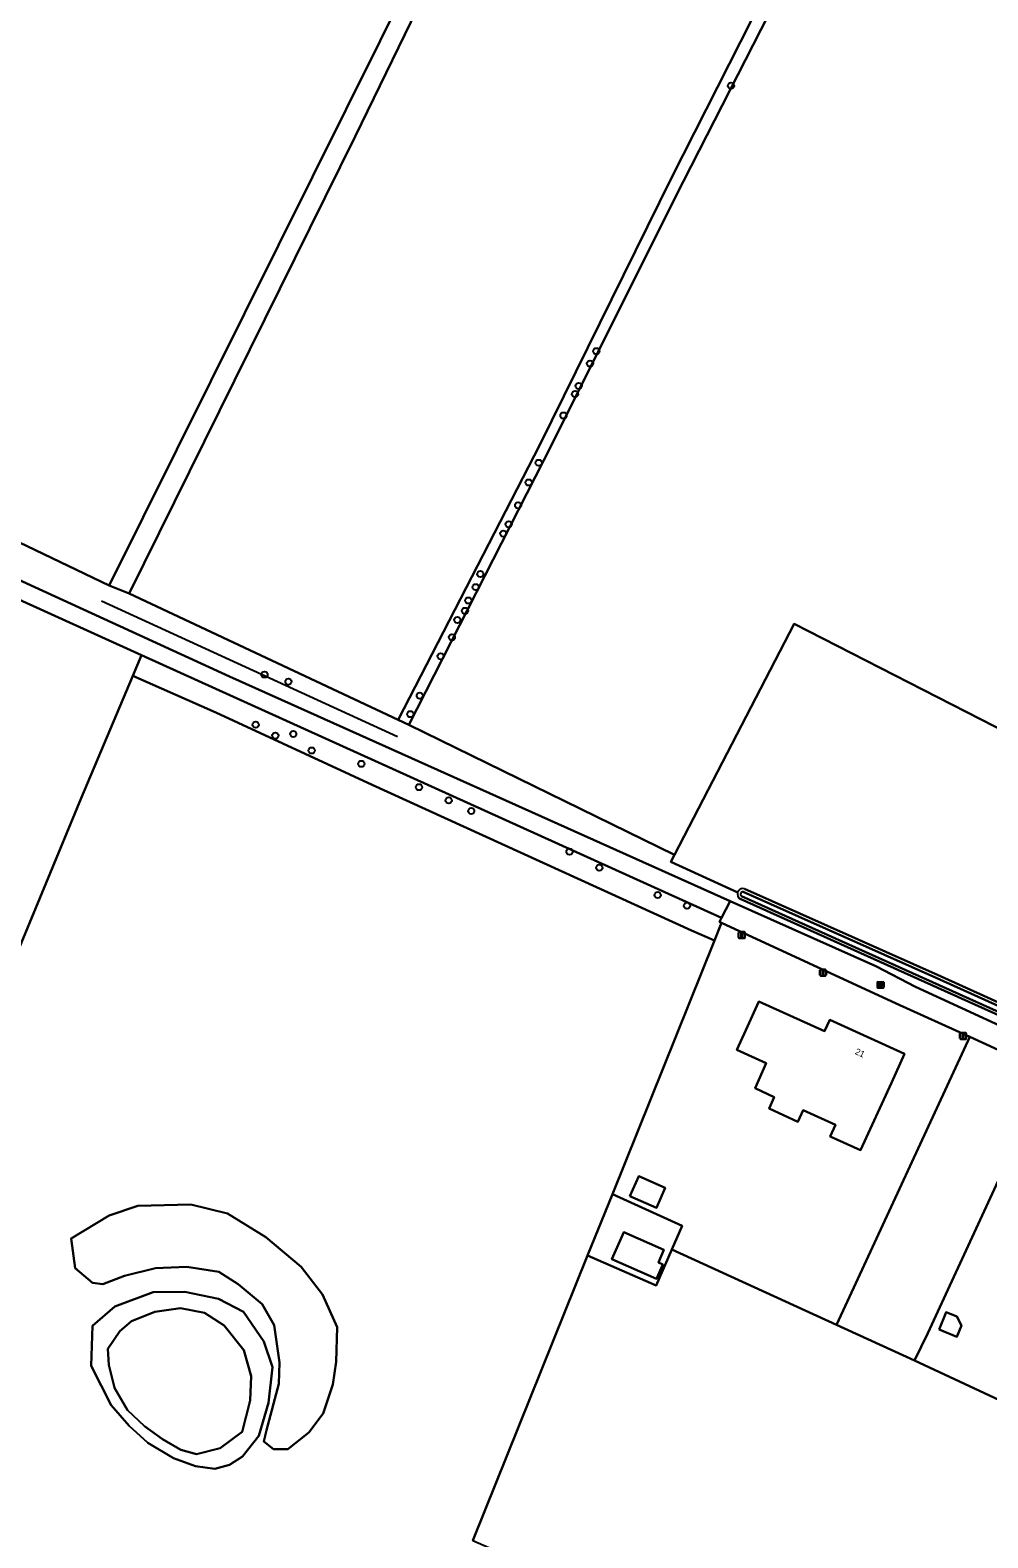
# Model space of a CAD drawing. Extents: x 155209 to 156748, y 385356 to 388487.
# Drawn here: x 155626.8 to 155777.4, y 385972.7 to 386210 of the extents above; entities that cross this region are included whole.
import ezdxf

# ---------------------------------------------------------------- set-up
doc = ezdxf.new("R2010")
doc.units = 0
for name, color, linetype in [('IMGEO_Boom', 7, 'Continuous'), ('IMGEO_Bouwland', 7, 'Continuous'), ('IMGEO_Erf', 7, 'Continuous'), ('IMGEO_Grasland_agrarisch', 7, 'Continuous'), ('IMGEO_Grasland_overig', 7, 'Continuous'), ('IMGEO_Groenvoorziening', 7, 'Continuous'), ('IMGEO_Hek', 7, 'Continuous'), ('IMGEO_Houtwal', 7, 'Continuous'), ('IMGEO_Lichtmast', 7, 'Continuous'), ('IMGEO_Loofbos', 7, 'Continuous'), ('IMGEO_Meer_plas_ven_vijver', 7, 'Continuous'), ('IMGEO_Oever', 7, 'Continuous'), ('IMGEO_Pand', 7, 'Continuous'), ('IMGEO_Pand_nummerreeks', 7, 'Continuous'), ('IMGEO_Rijbaan_lokaal_open', 7, 'Continuous'), ('IMGEO_Rioolput', 7, 'Continuous'), ('IMGEO_Waterloop', 7, 'Continuous')]:
    doc.layers.add(name, color=color, linetype=linetype)

msp = doc.modelspace()

# ---------------------------------------------------------------- linework, layer by layer
at = {"layer": 'IMGEO_Boom'}
for centre in [(155737.01, 386201.25), (155715.85, 386159.47), (155714.83, 386157.52), (155713.05, 386154), (155712.48, 386152.72), (155710.67, 386149.34), (155706.75, 386141.9), (155705.18, 386138.8), (155703.53, 386135.19), (155701.19, 386130.76), (155702.06, 386132.22), (155697.6, 386124.38), (155696.85, 386122.33), (155695.19, 386118.6), (155695.7, 386120.23), (155693.97, 386117.17), (155693.11, 386114.44), (155691.34, 386111.45), (155663.63, 386108.57), (155667.4, 386107.46), (155688.06, 386105.24), (155686.57, 386102.34), (155662.25, 386100.67), (155668.15, 386099.23), (155665.35, 386098.96), (155671.06, 386096.62), (155678.86, 386094.52), (155687.95, 386090.85), (155692.62, 386088.76), (155696.15, 386087.09), (155711.61, 386080.69), (155716.3, 386078.17), (155725.49, 386073.86), (155730.09, 386072.18)]:
    msp.add_circle(centre, 0.489, dxfattribs=at)
at = {"layer": 'IMGEO_Bouwland'}
msp.add_lwpolyline([(155732.88, 386307.56), (155732.51, 386306.84), (155728.48, 386298.72), (155729.99, 386297.98), (155708.82, 386256.23), (155704.36, 386246.76), (155689.59, 386217.32), (155677.91, 386193.26), (155642.36, 386121.35), (155684.67, 386101.45), (155706.93, 386144.74), (155727.66, 386186.74), (155753.06, 386236.87), (155775.47, 386280.18), (155776.23, 386279.85), (155779.73, 386287.01), (155779.22, 386287.22)], close=True, dxfattribs=at)
for points in [[(155823.3, 386267.6), (155780.71, 386286.96), (155779.89, 386287.34), (155779.73, 386287.01), (155776.23, 386279.85), (155777.11, 386279.38), (155729.56, 386186.22), (155707.56, 386142.3), (155686.33, 386100.64), (155728.14, 386080.19), (155746.94, 386116.53), (155834.92, 386071.53), (155850.53, 386101.48), (155869.89, 386139.18), (155897.23, 386193.45), (155910.33, 386221.05), (155911.39, 386223.4)], [(155606.88, 386138.08), (155639.2, 386122.59), (155681.83, 386208.31), (155708.36, 386261.64)]]:
    msp.add_lwpolyline(points, dxfattribs=at)
at = {"layer": 'IMGEO_Erf'}
for points in [[(155773.63, 386049.48), (155774.57, 386051.53), (155763.02, 386056.8), (155735.55, 386069.49), (155734.42, 386066.69), (155718.37, 386026.8), (155729.32, 386021.82), (155727.71, 386018.1), (155753.63, 386006.21), (155755.36, 386009.95)], [(155743, 386040.26), (155743.83, 386042.08), (155740.8, 386043.46), (155742.57, 386047.38), (155737.92, 386049.5), (155739.33, 386052.58), (155741.41, 386057.13), (155751.74, 386052.44), (155752.57, 386054.25), (155764.33, 386048.88), (155762.26, 386044.33), (155757.4, 386033.69), (155752.64, 386035.86), (155753.47, 386037.68), (155748.37, 386040.01), (155747.54, 386038.19)], [(155853.12, 385955.51), (155846.2, 385958.41), (155852.48, 385973.4), (155859.4, 385970.5), (155868.12, 385991.46), (155867.03, 385991.83), (155872.65, 386005.2), (155873.35, 386006.89), (155838.02, 386023), (155837.33, 386022.91), (155786.93, 386045.9), (155786.05, 386043.98), (155767.96, 386004.93), (155765.9, 386000.59), (155785.57, 385991.44), (155812.34, 385978.74), (155809.88, 385972.63), (155808.05, 385968.03), (155801.87, 385953.41), (155776.85, 385893.52), (155754.19, 385839.25), (155761.09, 385835.71), (155796.45, 385820.47), (155833.54, 385909.24)], [(155721.12, 386026.45), (155722.5, 386029.61), (155726.68, 386027.78), (155725.31, 386024.62)], [(155769.75, 386005.48), (155770.87, 386008.2), (155772.55, 386007.51), (155773.26, 386006.1), (155772.53, 386004.34)]]:
    msp.add_lwpolyline(points, close=True, dxfattribs=at)
at = {"layer": 'IMGEO_Grasland_agrarisch'}
msp.add_lwpolyline([(155785.57, 385991.44), (155765.9, 386000.59), (155753.63, 386006.21), (155727.71, 386018.1), (155725.24, 386012.39), (155714.46, 386017.11), (155696.41, 385972.27), (155741.48, 385952.55), (155743.7, 385951.54), (155749.58, 385965.64), (155754.11, 385964.04), (155732.64, 385910.57), (155730.66, 385911.1), (155728.52, 385911.95), (155741.86, 385947.1), (155694.61, 385967.79), (155668.77, 385903.59), (155694.55, 385871.44), (155696.18, 385869.04), (155744.28, 385815.73), (155754.19, 385839.25), (155776.85, 385893.52), (155771.51, 385895.43), (155790.82, 385938.59)], dxfattribs=at)
at = {"layer": 'IMGEO_Grasland_overig'}
for points in [[(155504.09, 386155.62), (155505.6, 386152.12), (155509.32, 386155.77), (155513.88, 386157.83), (155518.84, 386160.07), (155521.55, 386160.07), (155524.55, 386160.06), (155540.9, 386154.4), (155549.79, 386151.41), (155559.26, 386147.86), (155579.62, 386140.7), (155590.17, 386136.48), (155623.23, 386121.15), (155644.28, 386111.61), (155735.52, 386070.28), (155736.9, 386072.88), (155658.12, 386108.28)], [(155658.12, 386108.28), (155598.08, 386135.8), (155590.64, 386139.37), (155577.96, 386145.45), (155574.75, 386146.49), (155547.27, 386157.72)]]:
    msp.add_lwpolyline(points, dxfattribs=at)
for points in [[(155767.96, 386004.93), (155786.05, 386043.98), (155786.93, 386045.9), (155774.57, 386051.53), (155773.63, 386049.48), (155755.36, 386009.95), (155753.63, 386006.21), (155765.9, 386000.59)], [(155729.32, 386021.82), (155718.37, 386026.8), (155714.46, 386017.11), (155725.24, 386012.39), (155727.71, 386018.1)], [(155720.14, 386020.83), (155726.48, 386018.02), (155725.6, 386016.02), (155726.28, 386015.72), (155725.28, 386013.44), (155718.25, 386016.55)]]:
    msp.add_lwpolyline(points, close=True, dxfattribs=at)
at = {"layer": 'IMGEO_Groenvoorziening'}
for points in [[(155639.2, 386122.59), (155606.88, 386138.08), (155552.95, 386161.21), (155559.66, 386175.91), (155576.44, 386207.57), (155574.39, 386208.21), (155571.97, 386208.45), (155571.62, 386207.25), (155570.5, 386204.77), (155549.02, 386162.14)], [(155549.69, 386159.71), (155563.67, 386153.1), (155579.39, 386146.58), (155591.1, 386142.16), (155584.82, 386143.24), (155577.96, 386145.45), (155590.64, 386139.37), (155598.08, 386135.8), (155658.12, 386108.28), (155736.9, 386072.88), (155759.83, 386062.69), (155766.03, 386059.41), (155780.61, 386052.71), (155832.25, 386029.22), (155834.86, 386028.6), (155915.05, 385991.74), (155919.39, 385989.89), (155919.66, 385990.52), (155920.08, 385991.51), (155916.27, 385993.23), (155901.28, 386000), (155841.09, 386027.17), (155813.87, 386039.65)], [(155738.07, 386074.28), (155727.58, 386079.11), (155728.14, 386080.19), (155686.33, 386100.64), (155684.67, 386101.45), (155642.36, 386121.35), (155639.2, 386122.59)], [(155696.41, 385972.27), (155714.46, 386017.11), (155718.37, 386026.8), (155734.42, 386066.69), (155730.79, 386068.29), (155680.57, 386091.23), (155655.98, 386102.58), (155642.9, 386108.36), (155634.78, 386089.14), (155623.77, 386062.46), (155612.62, 386034.06), (155600.72, 386002.52), (155602.52, 386000), (155614.21, 385983.64), (155617.02, 385979.21), (155622.46, 385969.1)], [(155807.53, 386042.14), (155738.44, 386073.25)]]:
    msp.add_lwpolyline(points, dxfattribs=at)
for points in [[(155735.2, 386069.65), (155735.52, 386070.28), (155644.28, 386111.61), (155642.9, 386108.36), (155655.98, 386102.58), (155680.57, 386091.23), (155730.79, 386068.29), (155734.42, 386066.69), (155735.55, 386069.49)], [(155643.73, 386024.97), (155652.02, 386025.17), (155657.79, 386023.76), (155663.86, 386020.01), (155669.42, 386015.36), (155672.75, 386011.01), (155675.08, 386005.85), (155674.88, 386000.39), (155674.37, 385996.84), (155672.85, 385992.29), (155670.63, 385989.26), (155667.29, 385986.63), (155665.07, 385986.63), (155663.55, 385987.84), (155663.96, 385989.66), (155665.88, 385996.95), (155665.98, 386000.28), (155665.17, 386006.15), (155663.25, 386009.49), (155659.51, 386012.63), (155656.47, 386014.55), (155651.42, 386015.36), (155646.46, 386015.16), (155641.61, 386013.94), (155638.19, 386012.64), (155636.56, 386012.83), (155633.83, 386015.16), (155633.22, 386019.81), (155639.18, 386023.45)], [(155660.16, 385985.51), (155658.12, 385984.21), (155655.81, 385983.53), (155652.78, 385983.95), (155649.29, 385985.26), (155645.26, 385987.65), (155642.36, 385990.3), (155639.5, 385993.56), (155636.36, 385999.79), (155636.59, 386006.08), (155640.11, 386009.09), (155646.11, 386011.35), (155651.1, 386011.4), (155656.42, 386010.29), (155660.34, 386008.25), (155663.53, 386003.59), (155664.87, 385999.56), (155664.27, 385993.97), (155662.74, 385988.75)]]:
    msp.add_lwpolyline(points, close=True, dxfattribs=at)
msp.add_arc((155738.9, 386074), 0.881, 161.5794, 238.3689, dxfattribs=at)
at = {"layer": 'IMGEO_Hek'}
for points in [[(155637.98, 386120.16), (155684.58, 386098.82)], [(155728.14, 386080.19), (155746.94, 386116.53)], [(155680.57, 386091.23), (155655.98, 386102.58), (155642.9, 386108.36)], [(155680.57, 386091.23), (155730.79, 386068.29)], [(155734.42, 386066.69), (155730.79, 386068.29)]]:
    msp.add_lwpolyline(points, dxfattribs=at)
at = {"layer": 'IMGEO_Houtwal'}
for points in [[(155639.2, 386122.59), (155642.36, 386121.35), (155677.91, 386193.26), (155689.59, 386217.32), (155704.36, 386246.76), (155708.82, 386256.23), (155729.99, 386297.98), (155728.48, 386298.72), (155726.94, 386299.43), (155724.52, 386294.86), (155708.36, 386261.64), (155681.83, 386208.31)], [(155776.23, 386279.85), (155775.47, 386280.18), (155753.06, 386236.87), (155727.66, 386186.74), (155706.93, 386144.74), (155684.67, 386101.45), (155686.33, 386100.64), (155707.56, 386142.3), (155729.56, 386186.22), (155777.11, 386279.38)]]:
    msp.add_lwpolyline(points, close=True, dxfattribs=at)
at = {"layer": 'IMGEO_Lichtmast'}
for p, q in [((155738.21, 386067.16), (155738.21, 386067.96)), ((155738.21, 386067.96), (155738.21, 386067.16)), ((155738.31, 386068.06), (155739.1, 386068.06)), ((155739.1, 386068.06), (155738.31, 386068.06)), ((155739.1, 386067.06), (155738.31, 386067.06)), ((155738.31, 386067.06), (155739.1, 386067.06)), ((155739.2, 386067.96), (155739.2, 386067.16)), ((155739.2, 386067.16), (155739.2, 386067.96)), ((155751.01, 386061.25), (155751.01, 386062.05)), ((155751.01, 386062.05), (155751.01, 386061.25)), ((155751.11, 386062.15), (155751.89, 386062.15)), ((155751.89, 386062.15), (155751.11, 386062.15)), ((155751.99, 386062.05), (155751.99, 386061.25)), ((155751.99, 386061.25), (155751.99, 386062.05)), ((155751.89, 386061.15), (155751.11, 386061.15)), ((155751.11, 386061.15), (155751.89, 386061.15)), ((155773.14, 386052.18), (155773.93, 386052.18)), ((155773.93, 386052.18), (155773.14, 386052.18)), ((155773.04, 386051.28), (155773.04, 386052.08)), ((155773.04, 386052.08), (155773.04, 386051.28)), ((155773.93, 386051.18), (155773.14, 386051.18)), ((155773.14, 386051.18), (155773.93, 386051.18)), ((155774.03, 386052.08), (155774.03, 386051.28)), ((155774.03, 386051.28), (155774.03, 386052.08))]:
    msp.add_line(p, q, dxfattribs=at)
for points in [[(155738.63, 386067.93), (155738.78, 386067.93), (155738.78, 386067.18), (155738.63, 386067.18), (155738.63, 386067.93)], [(155751.43, 386062.03), (155751.58, 386062.03), (155751.58, 386061.28), (155751.43, 386061.28), (155751.43, 386062.03)], [(155773.46, 386052.06), (155773.61, 386052.06), (155773.61, 386051.31), (155773.46, 386051.31), (155773.46, 386052.06)]]:
    msp.add_lwpolyline(points, dxfattribs=at)
for centre, start, end in [((155738.31, 386067.96), 90, 180), ((155738.31, 386067.96), 90, 180), ((155738.31, 386067.16), 180, 270), ((155738.31, 386067.16), 180, 270), ((155739.1, 386067.96), 0, 90), ((155739.1, 386067.96), 360, 90), ((155739.1, 386067.16), 270, 0), ((155739.1, 386067.16), 270, 0), ((155751.11, 386062.05), 90, 180), ((155751.11, 386062.05), 90, 180), ((155751.89, 386062.05), 0, 90), ((155751.89, 386062.05), 360, 90), ((155751.11, 386061.25), 180, 270), ((155751.11, 386061.25), 180, 270), ((155751.89, 386061.25), 270, 0), ((155751.89, 386061.25), 270, 0), ((155773.14, 386052.08), 90, 180), ((155773.14, 386052.08), 90, 180), ((155773.93, 386052.08), 0, 90), ((155773.93, 386052.08), 360, 90), ((155773.14, 386051.28), 180, 270), ((155773.14, 386051.28), 180, 270), ((155773.93, 386051.28), 270, 0), ((155773.93, 386051.28), 270, 0)]:
    msp.add_arc(centre, 0.1, start, end, dxfattribs=at)
at = {"layer": 'IMGEO_Loofbos'}
for points in [[(155642.9, 386108.36), (155644.28, 386111.61), (155623.23, 386121.15), (155590.17, 386136.48), (155577.59, 386140.01), (155524.61, 386153.45), (155547.77, 386103.46), (155550.82, 386095.86), (155552.73, 386090.35), (155554.74, 386085.49), (155557.92, 386078.77), (155562.83, 386070.3), (155563.7, 386067.74), (155564.93, 386064.75), (155568.14, 386057.92), (155570.58, 386052.33), (155572.95, 386047.52), (155579.19, 386036.04), (155588.18, 386021.54), (155595.93, 386009.42), (155600.72, 386002.52), (155612.62, 386034.06), (155623.77, 386062.46), (155634.78, 386089.14)], [(155670.63, 385989.26), (155672.85, 385992.29), (155674.37, 385996.84), (155674.88, 386000.39), (155675.08, 386005.85), (155672.75, 386011.01), (155669.42, 386015.36), (155663.86, 386020.01), (155657.79, 386023.76), (155652.02, 386025.17), (155643.73, 386024.97), (155639.18, 386023.45), (155633.22, 386019.81), (155633.83, 386015.16), (155636.56, 386012.83), (155638.19, 386012.64), (155641.61, 386013.94), (155646.46, 386015.16), (155651.42, 386015.36), (155656.47, 386014.55), (155659.51, 386012.63), (155663.25, 386009.49), (155665.17, 386006.15), (155665.98, 386000.28), (155665.88, 385996.95), (155663.96, 385989.66), (155663.55, 385987.84), (155665.07, 385986.63), (155667.29, 385986.63)]]:
    msp.add_lwpolyline(points, close=True, dxfattribs=at)
for points in [[(155821.1, 386039.46), (155837.21, 386070.36), (155834.92, 386071.53), (155746.94, 386116.53), (155728.14, 386080.19), (155727.58, 386079.11), (155738.07, 386074.28)], [(155739.12, 386074.85), (155770.1, 386061.03), (155808.28, 386043.75)]]:
    msp.add_lwpolyline(points, dxfattribs=at)
msp.add_arc((155738.9, 386074), 0.879, 75.7492, 161.4105, dxfattribs=at)
at = {"layer": 'IMGEO_Meer_plas_ven_vijver'}
msp.add_lwpolyline([(155652.95, 385985.88), (155656.66, 385986.82), (155660.13, 385989.36), (155661.38, 385994.3), (155661.51, 385998.14), (155660.36, 386002.25), (155657.26, 386006.09), (155654.21, 386008.12), (155650.43, 386008.82), (155646.36, 386008.26), (155642.71, 386006.78), (155640.89, 386005.23), (155639.01, 386002.45), (155639.15, 385999.9), (155640.03, 385996.29), (155642.1, 385992.78), (155644.74, 385990.27), (155647.61, 385988.2), (155650.47, 385986.56)], close=True, dxfattribs=at)
at = {"layer": 'IMGEO_Oever'}
for points in [[(155807.73, 386042.6), (155738.68, 386073.7)], [(155738.96, 386074.38), (155769.89, 386060.57), (155808.06, 386043.3)], [(155770.1, 386061.03), (155739.12, 386074.85)], [(155738.44, 386073.25), (155807.53, 386042.14)], [(155808.28, 386043.75), (155770.1, 386061.03)]]:
    msp.add_lwpolyline(points, dxfattribs=at)
for points in [[(155660.16, 385985.51), (155662.74, 385988.75), (155664.27, 385993.97), (155664.87, 385999.56), (155663.53, 386003.59), (155660.34, 386008.25), (155656.42, 386010.29), (155651.1, 386011.4), (155646.11, 386011.35), (155640.11, 386009.09), (155636.59, 386006.08), (155636.36, 385999.79), (155639.5, 385993.56), (155642.36, 385990.3), (155645.26, 385987.65), (155649.29, 385985.26), (155652.78, 385983.95), (155655.81, 385983.53), (155658.12, 385984.21)], [(155652.95, 385985.88), (155650.47, 385986.56), (155647.61, 385988.2), (155644.74, 385990.27), (155642.1, 385992.78), (155640.03, 385996.29), (155639.15, 385999.9), (155639.01, 386002.45), (155640.89, 386005.23), (155642.71, 386006.78), (155646.36, 386008.26), (155650.43, 386008.82), (155654.21, 386008.12), (155657.26, 386006.09), (155660.36, 386002.25), (155661.51, 385998.14), (155661.38, 385994.3), (155660.13, 385989.36), (155656.66, 385986.82)]]:
    msp.add_lwpolyline(points, close=True, dxfattribs=at)
for radius, start, end in [(0.881, 161.5794, 238.3689), (0.879, 75.7492, 161.4105), (0.377, 80.8048, 234.7824)]:
    msp.add_arc((155738.9, 386074), radius, start, end, dxfattribs=at)
at = {"layer": 'IMGEO_Pand'}
for points in [[(155737.92, 386049.5), (155742.57, 386047.38), (155740.8, 386043.46), (155743.83, 386042.08), (155743, 386040.26), (155747.54, 386038.19), (155748.37, 386040.01), (155753.47, 386037.68), (155752.64, 386035.86), (155757.4, 386033.69), (155762.26, 386044.33), (155764.33, 386048.88), (155752.57, 386054.25), (155751.74, 386052.44), (155741.41, 386057.13), (155739.33, 386052.58)], [(155721.12, 386026.45), (155725.31, 386024.62), (155726.68, 386027.78), (155722.5, 386029.61)], [(155725.28, 386013.44), (155726.28, 386015.72), (155725.6, 386016.02), (155726.48, 386018.02), (155720.14, 386020.83), (155718.25, 386016.55)], [(155769.75, 386005.48), (155772.53, 386004.34), (155773.26, 386006.1), (155772.55, 386007.51), (155770.87, 386008.2)]]:
    msp.add_lwpolyline(points, close=True, dxfattribs=at)
at = {"layer": 'IMGEO_Rijbaan_lokaal_open'}
msp.add_lwpolyline([(155780.61, 386052.71), (155766.03, 386059.41), (155759.83, 386062.69), (155736.9, 386072.88), (155735.52, 386070.28), (155735.2, 386069.65), (155735.55, 386069.49), (155763.02, 386056.8), (155774.57, 386051.53), (155786.93, 386045.9), (155837.33, 386022.91), (155838.02, 386023), (155873.35, 386006.89), (155888.76, 386000), (155913.8, 385988.81), (155915.05, 385991.74), (155834.86, 386028.6), (155832.25, 386029.22)], close=True, dxfattribs=at)
at = {"layer": 'IMGEO_Rioolput'}
for p, q in [((155760.05, 386059.31), (155760.05, 386060.16)), ((155760.12, 386060.23), (155760.98, 386060.23)), ((155760.98, 386059.23), (155760.12, 386059.23)), ((155760.31, 386059.73), (155760.31, 386059.74)), ((155760.35, 386059.78), (155760.75, 386059.78)), ((155760.74, 386059.69), (155760.35, 386059.69)), ((155760.56, 386059.45), (155760.53, 386059.45)), ((155760.54, 386060.01), (155760.56, 386060.01)), ((155760.79, 386059.74), (155760.79, 386059.73)), ((155761.05, 386060.16), (155761.05, 386059.31))]:
    msp.add_line(p, q, dxfattribs=at)
for points in [[(155760.05, 386059.31), (155760.05, 386060.16)], [(155760.12, 386060.23), (155760.98, 386060.23)], [(155760.98, 386059.23), (155760.12, 386059.23)], [(155761.05, 386060.16), (155761.05, 386059.31)]]:
    msp.add_lwpolyline(points, dxfattribs=at)
for centre, radius, start, end in [((155760.12, 386060.16), 0.0765, 91.552, 178.448), ((155760.12, 386060.16), 0.0765, 91.552, 178.448), ((155760.12, 386059.31), 0.0765, 181.552, 268.448), ((155760.12, 386059.31), 0.0765, 181.552, 268.448), ((155760.35, 386059.74), 0.0403, 85.8775, 175.7526), ((155760.34, 386059.73), 0.0366, 178.938, 274.7102), ((155760.75, 386059.73), 0.043, 264.8664, 352.4533), ((155760.75, 386059.74), 0.0386, 1.7309, 96.639), ((155760.97, 386060.16), 0.0765, 1.552, 88.448), ((155760.97, 386060.16), 0.0765, 1.552, 88.448), ((155760.97, 386059.31), 0.0765, 271.552, 358.448), ((155760.97, 386059.31), 0.0765, 271.552, 358.448)]:
    msp.add_arc(centre, radius, start, end, dxfattribs=at)
for centre, major_axis, ratio, start_param, end_param in [((155760.54, 386059.73), (-0.387, 0.002), 0.722429, 4.712389, 7.853982), ((155760.56, 386059.73), (-0.39, 0.002), 0.717154, 1.570796, 4.712389)]:
    msp.add_ellipse(centre, major_axis=major_axis, ratio=ratio, start_param=start_param, end_param=end_param, dxfattribs=at)
at = {"layer": 'IMGEO_Waterloop'}
for points in [[(155738.68, 386073.7), (155807.73, 386042.6)], [(155808.06, 386043.3), (155769.89, 386060.57), (155738.96, 386074.38)]]:
    msp.add_lwpolyline(points, dxfattribs=at)
msp.add_arc((155738.9, 386074), 0.377, 80.8048, 234.7824, dxfattribs=at)

# ---------------------------------------------------------------- texts
at = {"layer": 'IMGEO_Pand_nummerreeks'}
msp.add_text('21', height=1, rotation=335.4768, dxfattribs=at).set_placement((155756.44, 386048.88))

doc.saveas('drawing.dxf')
